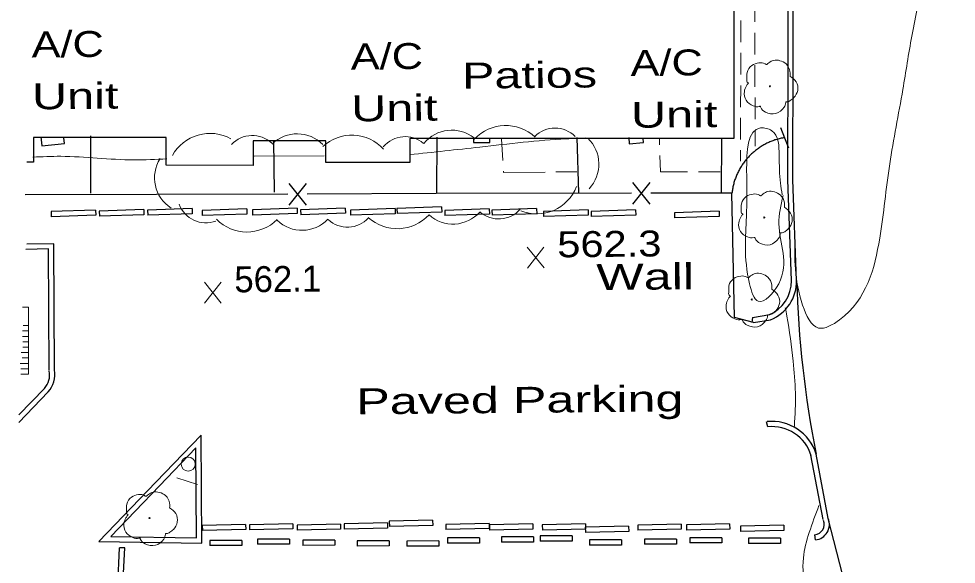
# Model space of a CAD drawing. Extents: x 2361708 to 2370558, y 6977955 to 6991887.
# Drawn here: x 2365807 to 2365980.4, y 6986115.3 to 6986216.2 of the extents above; entities that cross this region are included whole.
import ezdxf

# ---------------------------------------------------------------- set-up
doc = ezdxf.new("R2010")
doc.units = 0
doc.header["$LTSCALE"] = 1.9
for name, color, linetype, lineweight in [('11', 7, 'Continuous', 25), ('13', 7, 'Continuous', 13), ('14', 7, 'Continuous', 13), ('16', 7, 'Continuous', 13), ('17', 7, 'Continuous', 25), ('18', 7, 'Continuous', 25), ('2', 7, 'Continuous', 25), ('20', 7, 'Continuous', 25), ('23', 7, 'Continuous', 25), ('29', 7, 'Continuous', 13), ('31', 7, 'Continuous', 13), ('35', 7, 'Continuous', 13), ('9', 7, 'Continuous', 13)]:
    doc.layers.add(name, color=color, linetype=linetype, lineweight=lineweight)

msp = doc.modelspace()

# ---------------------------------------------------------------- linework, layer by layer
at = {"layer": '11'}
msp.add_lwpolyline([(2365809.437, 6986237.555), (2365868.14, 6986237.564), (2365868.14, 6986231.264), (2365939.283, 6986231.271), (2365939.287, 6986194.099), (2365879.304, 6986194.098), (2365879.297, 6986189.638), (2365863.756, 6986189.65), (2365863.757, 6986193.67), (2365850.337, 6986193.673), (2365850.33, 6986189.112), (2365834.249, 6986189.129), (2365834.25, 6986194.26), (2365809.669, 6986194.285), (2365809.663, 6986189.695), (2365808.423, 6986189.693)], dxfattribs=at)
at = {"layer": '13'}
for p, q in [((2365943.134, 6986219.657), (2365943.142, 6986215.657)), ((2365940.548, 6986211.912), (2365940.56, 6986215.913)), ((2365943.151, 6986213.657), (2365943.159, 6986209.657)), ((2365940.535, 6986205.912), (2365940.547, 6986209.912)), ((2365943.158, 6986207.657), (2365943.166, 6986203.657)), ((2365940.522, 6986199.911), (2365940.534, 6986203.911)), ((2365943.175, 6986201.657), (2365943.183, 6986197.656)), ((2365940.509, 6986193.911), (2365940.521, 6986197.911)), ((2365943.182, 6986195.657), (2365943.191, 6986192.646)), ((2365940.507, 6986189.911), (2365940.508, 6986191.91))]:
    msp.add_line(p, q, dxfattribs=at)
at = {"layer": '14'}
for p, q in [((2365896.265, 6986194.04), (2365896.493, 6986190.042)), ((2365925.528, 6986192.918), (2365925.486, 6986194.108)), ((2365906.355, 6986187.895), (2365910.234, 6986187.942)), ((2365936.715, 6986187.924), (2365932.715, 6986187.936)), ((2365840.012, 6986130.091), (2365836.21, 6986131.315))]:
    msp.add_line(p, q, dxfattribs=at)
for points in [[(2365930.715, 6986187.937), (2365925.685, 6986187.95), (2365925.587, 6986190.919)], [(2365896.612, 6986188.043), (2365896.625, 6986187.773), (2365904.355, 6986187.866)]]:
    msp.add_lwpolyline(points, dxfattribs=at)
at = {"layer": '16'}
for p, q in [((2365808.758, 6986162.875), (2365807.618, 6986162.874)), ((2365808.746, 6986150.485), (2365808.758, 6986162.875)), ((2365808.75, 6986158.485), (2365807.66, 6986158.485)), ((2365808.75, 6986159.485), (2365807.76, 6986159.486)), ((2365808.759, 6986157.485), (2365807.669, 6986157.485)), ((2365808.749, 6986156.484), (2365807.679, 6986156.484)), ((2365808.748, 6986155.485), (2365807.688, 6986155.485)), ((2365808.748, 6986154.485), (2365807.377, 6986154.492)), ((2365808.757, 6986153.485), (2365807.607, 6986153.484)), ((2365808.747, 6986152.485), (2365807.187, 6986152.48)), ((2365808.747, 6986151.485), (2365807.306, 6986151.481)), ((2365808.746, 6986150.485), (2365807.316, 6986150.481))]:
    msp.add_line(p, q, dxfattribs=at)
at = {"layer": '17'}
for p, q in [((2365820.287, 6986183.996), (2365820.316, 6986194.607)), ((2365854.287, 6986184.189), (2365854.146, 6986193.739)), ((2365884.28, 6986184.005), (2365884.382, 6986194.347)), ((2365910.551, 6986184.045), (2365910.294, 6986194.273)), ((2365936.988, 6986193.997), (2365936.932, 6986184.156)), ((2365923.714, 6986185.931), (2365920.512, 6986181.92)), ((2365920.514, 6986185.92), (2365923.712, 6986181.93)), ((2365856.902, 6986185.775), (2365860.12, 6986181.785)), ((2365860.102, 6986185.785), (2365856.92, 6986181.774)), ((2365856.711, 6986183.803), (2365808.161, 6986183.64)), ((2365938.914, 6986183.985), (2365923.913, 6986183.962))]:
    msp.add_line(p, q, dxfattribs=at)
msp.add_lwpolyline([(2365920.313, 6986183.958), (2365884.172, 6986183.894), (2365860.311, 6986183.817)], dxfattribs=at)
at = {"layer": '18'}
for points in [[(2365947.918, 6986196.101), (2365948.646, 6986194.238), (2365949.374, 6986192.375)], [(2365948.646, 6986194.238), (2365948.447, 6986194.206), (2365948.247, 6986194.165), (2365948.047, 6986194.123), (2365947.848, 6986194.081), (2365947.648, 6986194.029), (2365947.459, 6986193.977), (2365947.259, 6986193.925), (2365947.06, 6986193.873), (2365946.87, 6986193.812), (2365946.681, 6986193.74), (2365946.481, 6986193.678), (2365946.292, 6986193.606), (2365946.103, 6986193.524), (2365945.914, 6986193.452), (2365945.734, 6986193.371), (2365945.545, 6986193.279), (2365945.366, 6986193.197), (2365945.187, 6986193.106), (2365944.998, 6986193.004), (2365944.818, 6986192.912), (2365944.649, 6986192.81), (2365944.471, 6986192.708), (2365944.301, 6986192.597), (2365944.132, 6986192.495), (2365943.954, 6986192.373), (2365943.794, 6986192.262), (2365943.626, 6986192.14), (2365943.457, 6986192.018), (2365943.298, 6986191.897), (2365943.139, 6986191.765), (2365942.99, 6986191.644), (2365942.832, 6986191.512), (2365942.683, 6986191.371), (2365942.534, 6986191.24), (2365942.386, 6986191.098), (2365942.237, 6986190.957), (2365942.098, 6986190.806), (2365941.96, 6986190.655), (2365941.821, 6986190.513), (2365941.683, 6986190.352), (2365941.554, 6986190.2), (2365941.426, 6986190.039), (2365941.297, 6986189.888), (2365941.179, 6986189.727), (2365941.05, 6986189.555), (2365940.932, 6986189.395), (2365940.823, 6986189.224), (2365940.715, 6986189.053), (2365940.597, 6986188.881), (2365940.499, 6986188.71), (2365940.39, 6986188.53), (2365940.292, 6986188.358), (2365940.193, 6986188.178), (2365940.105, 6986187.997), (2365940.017, 6986187.816), (2365939.929, 6986187.635), (2365939.841, 6986187.444), (2365939.762, 6986187.263), (2365939.684, 6986187.073), (2365939.606, 6986186.882), (2365939.538, 6986186.691), (2365939.469, 6986186.501), (2365939.411, 6986186.31), (2365939.343, 6986186.109), (2365939.285, 6986185.919), (2365939.237, 6986185.719), (2365939.189, 6986185.528), (2365939.141, 6986185.327), (2365939.093, 6986185.127), (2365939.055, 6986184.927), (2365939.016, 6986184.726), (2365938.988, 6986184.526), (2365938.96, 6986184.326), (2365938.932, 6986184.125), (2365938.914, 6986183.985)]]:
    msp.add_lwpolyline(points, dxfattribs=at)
at = {"layer": '2'}
for p, q in [((2365821.178, 6986180.844), (2365812.93, 6986180.556)), ((2365821.178, 6986180.844), (2365821.207, 6986179.885)), ((2365830.087, 6986180.949), (2365821.839, 6986180.661)), ((2365821.839, 6986180.661), (2365821.868, 6986179.701)), ((2365830.087, 6986180.949), (2365830.116, 6986179.99)), ((2365839.036, 6986181.124), (2365830.788, 6986180.836)), ((2365830.788, 6986180.836), (2365830.817, 6986179.876)), ((2365839.036, 6986181.124), (2365839.065, 6986180.164)), ((2365849.127, 6986181.07), (2365840.879, 6986180.782)), ((2365840.879, 6986180.782), (2365840.908, 6986179.822)), ((2365849.127, 6986181.07), (2365849.156, 6986180.111)), ((2365858.446, 6986181.169), (2365850.199, 6986180.881)), ((2365850.199, 6986180.881), (2365850.227, 6986179.921)), ((2365858.446, 6986181.169), (2365858.475, 6986180.209)), ((2365867.357, 6986181.204), (2365859.109, 6986180.915)), ((2365859.109, 6986180.915), (2365859.138, 6986179.956)), ((2365867.357, 6986181.204), (2365867.385, 6986180.244)), ((2365876.577, 6986181.132), (2365868.33, 6986180.843)), ((2365868.33, 6986180.843), (2365868.359, 6986179.884)), ((2365876.577, 6986181.132), (2365876.607, 6986180.172)), ((2365885.175, 6986181.444), (2365876.927, 6986181.155)), ((2365876.927, 6986181.155), (2365876.956, 6986180.196)), ((2365885.175, 6986181.444), (2365885.204, 6986180.484)), ((2365894.008, 6986181.068), (2365885.761, 6986180.779)), ((2365885.761, 6986180.779), (2365885.79, 6986179.82)), ((2365894.008, 6986181.068), (2365894.038, 6986180.108)), ((2365902.749, 6986181.141), (2365894.501, 6986180.852)), ((2365894.501, 6986180.852), (2365894.53, 6986179.892)), ((2365902.749, 6986181.141), (2365902.778, 6986180.181)), ((2365912.281, 6986180.881), (2365904.034, 6986180.593)), ((2365912.281, 6986180.881), (2365912.311, 6986179.922)), ((2365921.082, 6986180.885), (2365912.835, 6986180.597)), ((2365921.082, 6986180.885), (2365921.111, 6986179.926)), ((2365936.525, 6986180.642), (2365928.277, 6986180.354)), ((2365936.525, 6986180.642), (2365936.554, 6986179.682)), ((2365812.93, 6986180.556), (2365812.959, 6986179.596)), ((2365821.207, 6986179.885), (2365812.959, 6986179.596)), ((2365830.116, 6986179.99), (2365821.868, 6986179.701)), ((2365839.065, 6986180.164), (2365830.817, 6986179.876)), ((2365849.156, 6986180.111), (2365840.908, 6986179.822)), ((2365858.475, 6986180.209), (2365850.227, 6986179.921)), ((2365867.385, 6986180.244), (2365859.138, 6986179.956)), ((2365876.607, 6986180.172), (2365868.359, 6986179.884)), ((2365885.204, 6986180.484), (2365876.956, 6986180.196)), ((2365894.038, 6986180.108), (2365885.79, 6986179.82)), ((2365902.778, 6986180.181), (2365894.53, 6986179.892)), ((2365904.034, 6986180.593), (2365904.063, 6986179.633)), ((2365912.311, 6986179.922), (2365904.063, 6986179.633)), ((2365912.835, 6986180.597), (2365912.863, 6986179.637)), ((2365921.111, 6986179.926), (2365912.863, 6986179.637)), ((2365928.277, 6986180.354), (2365928.307, 6986179.394)), ((2365936.554, 6986179.682), (2365928.307, 6986179.394)), ((2365942.742, 6986161), (2365942.591, 6986160.049)), ((2365942.742, 6986161), (2365945.918, 6986161.501)), ((2365942.891, 6986160.052), (2365946.067, 6986160.552)), ((2365806.987, 6986142.947), (2365811.711, 6986147.862)), ((2365806.951, 6986141.517), (2365812.407, 6986147.199)), ((2365945.525, 6986140.746), (2365945.276, 6986141.673)), ((2365956.727, 6986123.782), (2365954.484, 6986135.681)), ((2365955.779, 6986123.603), (2365953.536, 6986135.502)), ((2365883.517, 6986123.465), (2365875.508, 6986123.279)), ((2365883.517, 6986123.465), (2365883.536, 6986122.505)), ((2365965.003, 6986091.709), (2365956.727, 6986123.782)), ((2365848.922, 6986122.686), (2365840.914, 6986122.5)), ((2365840.914, 6986122.5), (2365840.933, 6986121.54)), ((2365848.942, 6986121.726), (2365840.933, 6986121.54)), ((2365848.922, 6986122.686), (2365848.942, 6986121.726)), ((2365857.651, 6986122.819), (2365849.643, 6986122.632)), ((2365849.643, 6986122.632), (2365849.662, 6986121.673)), ((2365857.671, 6986121.859), (2365849.662, 6986121.673)), ((2365857.651, 6986122.819), (2365857.671, 6986121.859)), ((2365866.453, 6986122.752), (2365858.444, 6986122.566)), ((2365858.444, 6986122.566), (2365858.463, 6986121.606)), ((2365866.472, 6986121.792), (2365858.463, 6986121.606)), ((2365866.453, 6986122.752), (2365866.472, 6986121.792)), ((2365875.151, 6986122.965), (2365867.143, 6986122.779)), ((2365867.143, 6986122.779), (2365867.161, 6986121.819)), ((2365875.17, 6986122.006), (2365867.161, 6986121.819)), ((2365875.151, 6986122.965), (2365875.17, 6986122.006)), ((2365875.508, 6986123.279), (2365875.527, 6986122.319)), ((2365883.536, 6986122.505), (2365875.527, 6986122.319)), ((2365893.983, 6986122.885), (2365885.974, 6986122.698)), ((2365885.974, 6986122.698), (2365885.993, 6986121.739)), ((2365894.002, 6986121.925), (2365885.993, 6986121.739)), ((2365893.983, 6986122.885), (2365894.002, 6986121.925)), ((2365902.054, 6986122.792), (2365894.045, 6986122.605)), ((2365894.045, 6986122.605), (2365894.064, 6986121.646)), ((2365902.073, 6986121.832), (2365894.064, 6986121.646)), ((2365902.054, 6986122.792), (2365902.073, 6986121.832)), ((2365911.825, 6986122.774), (2365903.816, 6986122.588)), ((2365903.816, 6986122.588), (2365903.835, 6986121.628)), ((2365911.844, 6986121.815), (2365903.835, 6986121.628)), ((2365919.789, 6986122.34), (2365911.78, 6986122.154)), ((2365911.78, 6986122.154), (2365911.8, 6986121.194)), ((2365911.825, 6986122.774), (2365911.844, 6986121.815)), ((2365919.789, 6986122.34), (2365919.808, 6986121.38)), ((2365929.505, 6986122.743), (2365921.497, 6986122.557)), ((2365921.497, 6986122.557), (2365921.516, 6986121.597)), ((2365929.525, 6986121.783), (2365921.516, 6986121.597)), ((2365929.505, 6986122.743), (2365929.525, 6986121.783)), ((2365938.486, 6986122.778), (2365930.477, 6986122.592)), ((2365930.477, 6986122.592), (2365930.496, 6986121.632)), ((2365938.505, 6986121.818), (2365930.496, 6986121.632)), ((2365938.486, 6986122.778), (2365938.505, 6986121.818)), ((2365948.498, 6986122.553), (2365940.49, 6986122.367)), ((2365940.49, 6986122.367), (2365940.509, 6986121.407)), ((2365948.498, 6986122.553), (2365948.518, 6986121.593)), ((2365851.128, 6986119.976), (2365851.127, 6986119.016)), ((2365857.048, 6986119.983), (2365851.128, 6986119.976)), ((2365857.048, 6986119.983), (2365857.048, 6986119.022)), ((2365886.308, 6986120.191), (2365886.307, 6986119.231)), ((2365892.228, 6986120.197), (2365886.308, 6986120.191)), ((2365892.228, 6986120.197), (2365892.227, 6986119.237)), ((2365896.297, 6986120.386), (2365896.296, 6986119.426)), ((2365902.217, 6986120.393), (2365896.297, 6986120.386)), ((2365902.217, 6986120.393), (2365902.216, 6986119.433)), ((2365909.356, 6986120.561), (2365903.435, 6986120.554)), ((2365903.435, 6986120.554), (2365903.435, 6986119.594)), ((2365909.356, 6986120.561), (2365909.355, 6986119.601)), ((2365919.808, 6986121.38), (2365911.8, 6986121.194)), ((2365922.742, 6986119.968), (2365922.741, 6986119.008)), ((2365928.662, 6986119.974), (2365922.742, 6986119.968)), ((2365928.662, 6986119.974), (2365928.661, 6986119.014)), ((2365931.1, 6986120.228), (2365931.099, 6986119.268)), ((2365937.02, 6986120.234), (2365931.1, 6986120.228)), ((2365937.02, 6986120.234), (2365937.019, 6986119.274)), ((2365948.518, 6986121.593), (2365940.509, 6986121.407)), ((2365941.951, 6986120.121), (2365941.95, 6986119.161)), ((2365947.872, 6986120.127), (2365941.951, 6986120.121)), ((2365947.872, 6986120.127), (2365947.871, 6986119.167)), ((2365954.375, 6986119.819), (2365954.256, 6986120.768)), ((2365825.245, 6986110.77), (2365825.602, 6986118.383)), ((2365826.563, 6986118.342), (2365825.602, 6986118.383)), ((2365826.205, 6986110.729), (2365826.563, 6986118.342)), ((2365842.32, 6986119.732), (2365842.319, 6986118.772)), ((2365848.24, 6986118.779), (2365842.319, 6986118.772)), ((2365848.24, 6986119.739), (2365842.32, 6986119.732)), ((2365848.24, 6986119.739), (2365848.24, 6986118.779)), ((2365857.048, 6986119.022), (2365851.127, 6986119.016)), ((2365859.511, 6986119.776), (2365859.51, 6986118.816)), ((2365865.43, 6986118.823), (2365859.51, 6986118.816)), ((2365865.43, 6986119.783), (2365859.511, 6986119.776)), ((2365865.43, 6986119.783), (2365865.43, 6986118.823)), ((2365869.562, 6986119.652), (2365869.561, 6986118.691)), ((2365875.482, 6986118.698), (2365869.561, 6986118.691)), ((2365875.483, 6986119.658), (2365869.562, 6986119.652)), ((2365875.483, 6986119.658), (2365875.482, 6986118.698)), ((2365878.753, 6986119.619), (2365878.752, 6986118.659)), ((2365884.672, 6986118.666), (2365878.752, 6986118.659)), ((2365884.673, 6986119.625), (2365878.753, 6986119.619)), ((2365884.673, 6986119.625), (2365884.672, 6986118.666)), ((2365892.227, 6986119.237), (2365886.307, 6986119.231)), ((2365902.216, 6986119.433), (2365896.296, 6986119.426)), ((2365909.355, 6986119.601), (2365903.435, 6986119.594)), ((2365912.543, 6986119.821), (2365912.542, 6986118.861)), ((2365918.462, 6986118.867), (2365912.542, 6986118.861)), ((2365918.463, 6986119.827), (2365912.543, 6986119.821)), ((2365918.463, 6986119.827), (2365918.462, 6986118.867)), ((2365928.661, 6986119.014), (2365922.741, 6986119.008)), ((2365937.019, 6986119.274), (2365931.099, 6986119.268)), ((2365947.871, 6986119.167), (2365941.95, 6986119.161))]:
    msp.add_line(p, q, dxfattribs=at)
for points in [[(2365949.918, 6986167.789), (2365949.23, 6986186.433), (2365949.368, 6986232.867)], [(2365950.877, 6986167.828), (2365950.19, 6986186.453), (2365950.328, 6986232.866)], [(2365942.891, 6986160.052), (2365939.352, 6986160.978), (2365938.914, 6986183.985)], [(2365813.549, 6986151.25), (2365813.426, 6986174.63), (2365808.457, 6986174.513)], [(2365812.589, 6986151.241), (2365812.476, 6986173.651), (2365808.256, 6986173.551)], [(2365840.805, 6986119.228), (2365840.675, 6986139.198), (2365832.327, 6986130.528)], [(2365839.835, 6986120.209), (2365839.727, 6986136.839), (2365833.003, 6986129.854)], [(2365832.327, 6986130.528), (2365821.751, 6986119.557), (2365840.805, 6986119.228)], [(2365833.003, 6986129.854), (2365823.972, 6986120.478), (2365839.835, 6986120.209)]]:
    msp.add_lwpolyline(points, dxfattribs=at)
for centre, radius, start, end in [((2365943.15, 6986167.709), 6.768, 292.17517, 0.88697), ((2365943.15, 6986167.709), 7.728, 292.17517, 0.88697), ((2366147.117, 6986173.566), 196.323, 181.67472, 191.12625), ((2365808.857, 6986150.385), 4.77, 318.09987, 10.44946), ((2365808.857, 6986150.385), 3.81, 318.09987, 10.44946), ((2365946.31, 6986133.213), 8.538, 16.80327, 95.94428), ((2365946.31, 6986133.213), 7.578, 16.80327, 95.94428), ((2365954.036, 6986122.7), 1.941, 276.70544, 21.8969), ((2365954.036, 6986122.7), 2.901, 276.70544, 21.8969)]:
    msp.add_arc(centre, radius, start, end, dxfattribs=at)
at = {"layer": '23'}
for p, q in [((2365811.058, 6986194.399), (2365811.234, 6986192.73)), ((2365891.076, 6986193.991), (2365891.071, 6986193.36)), ((2365919.815, 6986194.264), (2365919.916, 6986193.085))]:
    msp.add_line(p, q, dxfattribs=at)
for points in [[(2365811.234, 6986192.73), (2365815.42, 6986193.15), (2365815.31, 6986194.239)], [(2365891.071, 6986193.36), (2365894.132, 6986193.349), (2365894.133, 6986194.23)], [(2365919.916, 6986193.085), (2365922.564, 6986193.32), (2365922.496, 6986194.099)]]:
    msp.add_lwpolyline(points, dxfattribs=at)
at = {"layer": '29'}
for centre in [(2365945.936, 6986203.743), (2365944.897, 6986179.472), (2365942.571, 6986164.299), (2365831.15, 6986123.866)]:
    msp.add_circle(centre, 0.1, dxfattribs=at)
for centre, radius, start, end in [((2365897.051, 6986188.529), 7.96, 46.94275, 136.94275), ((2365842.334, 6986187.077), 7.96, 60.90853, 150.90853), ((2365850.173, 6986189.332), 5.304, 46.79714, 136.79714), ((2365858.47, 6986188.322), 6.636, 44.36255, 134.36255), ((2365868.594, 6986186.751), 7.96, 42.55703, 132.55703), ((2365887.081, 6986188.999), 6.636, 51.36799, 141.36799), ((2365906.159, 6986190.705), 5.304, 44.90086, 134.90086), ((2365878.46, 6986189.126), 5.304, 50.00295, 140.00295), ((2365907.651, 6986189.357), 6.636, 316.53602, 46.53602), ((2365838.704, 6986186.803), 6.636, 147.4126, 237.4126), ((2365902.757, 6986188.097), 7.96, 248.5143, 338.5143), ((2365841.59, 6986183.791), 5.304, 200.25494, 290.25494), ((2365895.735, 6986184.504), 5.304, 229.11124, 319.11124), ((2365849.177, 6986184.749), 7.96, 224.62859, 314.62859), ((2365859.377, 6986183.744), 6.636, 226.14325, 316.14325), ((2365867.773, 6986182.993), 5.304, 227.49206, 317.49206), ((2365876.99, 6986185.358), 7.96, 227.49206, 317.49206), ((2365887.295, 6986184.887), 6.636, 228.17591, 318.17591)]:
    msp.add_arc(centre, radius, start, end, dxfattribs=at)
for points in [[(2365941.97, 6986204.315), (2365941.99, 6986204.325), (2365941.909, 6986204.394), (2365941.673, 6986205.022), (2365941.711, 6986206.303), (2365942.599, 6986207.602), (2365943.904, 6986208.084), (2365945.026, 6986207.895), (2365945.257, 6986207.767), (2365945.327, 6986207.767), (2365945.377, 6986207.808), (2365945.724, 6986208.101), (2365946.59, 6986208.55), (2365947.8, 6986208.481), (2365948.916, 6986207.892), (2365949.65, 6986206.468), (2365949.658, 6986205.608)], [(2365949.647, 6986205.628), (2365950.788, 6986204.569), (2365951.073, 6986202.982), (2365950.366, 6986201.655), (2365949.711, 6986201.109), (2365949.043, 6986200.893), (2365948.893, 6986200.881), (2365948.874, 6986200.771), (2365948.552, 6986199.867), (2365947.014, 6986198.703), (2365945.121, 6986198.985), (2365944.222, 6986199.927), (2365944.15, 6986200.056), (2365944.031, 6986200.034), (2365942.819, 6986200.153), (2365941.55, 6986201.151), (2365941.205, 6986202.788), (2365941.575, 6986203.811), (2365941.9, 6986204.255), (2365941.97, 6986204.305)], [(2365940.931, 6986180.044), (2365940.951, 6986180.055), (2365940.87, 6986180.124), (2365940.634, 6986180.751), (2365940.672, 6986182.032), (2365941.56, 6986183.33), (2365942.865, 6986183.813), (2365943.987, 6986183.623), (2365944.218, 6986183.495), (2365944.288, 6986183.496), (2365944.338, 6986183.537), (2365944.685, 6986183.83), (2365945.551, 6986184.278), (2365946.761, 6986184.21), (2365947.877, 6986183.62), (2365948.611, 6986182.198), (2365948.619, 6986181.338)], [(2365948.609, 6986181.357), (2365949.749, 6986180.298), (2365950.034, 6986178.711), (2365949.327, 6986177.384), (2365948.672, 6986176.838), (2365948.004, 6986176.621), (2365947.854, 6986176.61), (2365947.835, 6986176.499), (2365947.513, 6986175.597), (2365945.975, 6986174.432), (2365944.082, 6986174.714), (2365943.183, 6986175.655), (2365943.111, 6986175.785), (2365942.992, 6986175.764), (2365941.78, 6986175.882), (2365940.511, 6986176.88), (2365940.166, 6986178.517), (2365940.536, 6986179.54), (2365940.861, 6986179.983), (2365940.931, 6986180.034)], [(2365938.605, 6986164.871), (2365938.625, 6986164.881), (2365938.544, 6986164.951), (2365938.309, 6986165.578), (2365938.347, 6986166.859), (2365939.234, 6986168.158), (2365940.539, 6986168.64), (2365941.661, 6986168.451), (2365941.893, 6986168.323), (2365941.962, 6986168.324), (2365942.012, 6986168.364), (2365942.359, 6986168.657), (2365943.225, 6986169.105), (2365944.436, 6986169.037), (2365945.552, 6986168.448), (2365946.285, 6986167.024), (2365946.293, 6986166.164)], [(2365946.283, 6986166.184), (2365947.423, 6986165.125), (2365947.708, 6986163.538), (2365947.001, 6986162.211), (2365946.346, 6986161.665), (2365945.678, 6986161.449), (2365945.528, 6986161.437), (2365945.509, 6986161.327), (2365945.188, 6986160.424), (2365943.649, 6986159.259), (2365941.756, 6986159.541), (2365940.857, 6986160.483), (2365940.786, 6986160.612), (2365940.666, 6986160.591), (2365939.455, 6986160.709), (2365938.186, 6986161.707), (2365937.84, 6986163.344), (2365938.21, 6986164.368), (2365938.536, 6986164.811), (2365938.606, 6986164.861)], [(2365827.184, 6986124.439), (2365827.204, 6986124.449), (2365827.124, 6986124.518), (2365826.888, 6986125.146), (2365826.926, 6986126.426), (2365827.813, 6986127.725), (2365829.119, 6986128.208), (2365830.241, 6986128.018), (2365830.472, 6986127.891), (2365830.542, 6986127.891), (2365830.592, 6986127.932), (2365830.939, 6986128.225), (2365831.805, 6986128.673), (2365833.015, 6986128.605), (2365834.131, 6986128.015), (2365834.865, 6986126.592), (2365834.872, 6986125.732)], [(2365834.863, 6986125.752), (2365836.003, 6986124.693), (2365836.288, 6986123.105), (2365835.58, 6986121.779), (2365834.926, 6986121.232), (2365834.257, 6986121.016), (2365834.108, 6986121.004), (2365834.089, 6986120.895), (2365833.767, 6986119.991), (2365832.228, 6986118.826), (2365830.336, 6986119.108), (2365829.437, 6986120.05), (2365829.365, 6986120.179), (2365829.245, 6986120.158), (2365828.034, 6986120.276), (2365826.765, 6986121.275), (2365826.419, 6986122.911), (2365826.789, 6986123.935), (2365827.115, 6986124.378), (2365827.184, 6986124.429)]]:
    msp.add_spline(points, degree=3, dxfattribs=at)
at = {"layer": '31'}
for p, q in [((2365904.164, 6986170.133), (2365901.047, 6986173.984)), ((2365901.083, 6986170.104), (2365904.127, 6986174.014)), ((2365844.423, 6986163.654), (2365841.305, 6986167.505)), ((2365841.342, 6986163.625), (2365844.386, 6986167.535))]:
    msp.add_line(p, q, dxfattribs=at)
at = {"layer": '35'}
msp.add_line((2365863.474, 6986190.908), (2365850.504, 6986190.814), dxfattribs=at)
for points in [[(2365950.55, 6986176.005), (2365951.991, 6986163.248), (2365954.952, 6986159.027), (2365958.837, 6986160.563), (2365966.244, 6986175.625), (2365968.094, 6986189.373), (2365970.532, 6986203.147), (2365972.179, 6986213.003), (2365976.645, 6986233.297), (2365979.304, 6986252.353), (2365979.825, 6986270.128), (2365982.408, 6986277.224), (2365983.705, 6986279.596)], [(2365948.368, 6986183.525), (2365947.598, 6986178.317), (2365947.563, 6986167.217), (2365943.784, 6986163.971), (2365942.163, 6986167.225), (2365941.595, 6986179.591), (2365941.632, 6986188.321), (2365944.219, 6986196.046), (2365946.294, 6986195.526), (2365947.657, 6986190.979), (2365947.886, 6986185.831), (2365948.207, 6986183.694)], [(2365911.865, 6986194.198), (2365908.276, 6986194.034), (2365892.28, 6986192.502), (2365879.293, 6986191.088)], [(2365834.368, 6986190.33), (2365828.249, 6986190.132), (2365814.722, 6986190.793), (2365809.564, 6986190.644)], [(2365950.454, 6986140.863), (2365950.655, 6986147.055), (2365950.23, 6986152.901), (2365949.07, 6986161.241), (2365948.775, 6986162.778)], [(2365951.825, 6986092.434), (2365951.599, 6986098.392), (2365952.245, 6986110.348), (2365952.126, 6986116.478), (2365953.212, 6986121.188), (2365955.004, 6986126.205)]]:
    msp.add_spline(points, degree=3, dxfattribs=at)
at = {"layer": '9'}
msp.add_circle((2365838.306, 6986133.855), 1.3, dxfattribs=at)

# ---------------------------------------------------------------- texts
at = {"layer": '14', "width": 1.4}
msp.add_text('Patios', height=4.8, rotation=0.545, dxfattribs=at).set_placement((2365888.997, 6986203.311))
at = {"layer": '18', "width": 1.45}
msp.add_text('Wall', height=4.8, rotation=0.545, dxfattribs=at).set_placement((2365913.823, 6986166.036))
at = {"layer": '2', "width": 1.45}
msp.add_text('Paved Parking', height=4.8, rotation=0.545, dxfattribs=at).set_placement((2365869.42, 6986143.042))
at = {"layer": '20'}
for s, width, p in [('A/C', 1.25, (2365809.338, 6986209.073)), ('A/C', 1.25, (2365868.392, 6986206.845)), ('A/C', 1.25, (2365920.166, 6986205.658)), ('Unit', 1.4, (2365809.43, 6986199.473)), ('Unit', 1.4, (2365868.484, 6986197.245)), ('Unit', 1.4, (2365920.257, 6986196.058))]:
    msp.add_text(s, height=4.8, rotation=0.545, dxfattribs=dict(at, width=width)).set_placement(p)
at = {"layer": '31', "width": 1.2}
msp.add_text('562.3', height=4.8, rotation=0.545, dxfattribs=at).set_placement((2365906.605, 6986172.097))
at = {"layer": '31'}
msp.add_text('562.1', height=4.8, rotation=0.545, dxfattribs=at).set_placement((2365846.864, 6986165.618))

doc.saveas('drawing.dxf')
